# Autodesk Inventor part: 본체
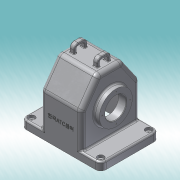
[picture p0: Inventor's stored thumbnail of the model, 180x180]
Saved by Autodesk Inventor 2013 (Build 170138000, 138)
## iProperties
Created: 2016-12
Part Number: 본체
Material: 알루미늄 6061
Document SubType Name: Modeling
Designer: dgall
Density: 2.71 g/cm^3
Mass: 1066.93 g
Surface Area: 1138.58 cm^2
Volume: 393.702 cm^3
Author: dgall
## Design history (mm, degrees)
sketch "스케치1"
  geometry: L1 (-75, 55)-(75, 55); L2 (75, 55)-(75, -55); L3 (75, -55)-(-75, -55); L4 (-75, -55)-(-75, 55); 3 further points
  constraints: 8 end point, 2 midpoint, 2 parallel, 1 horizontal, 1 horizontal alignment, 1 perpendicular, 1 vertical alignment
  dimensions: "d0" = 150 distance of L1.start L1.end; "d2" = 110 distance of L1.end L2.end
extrude "돌출1" new body sketch "스케치1" distance "d3" = 15; taper "d4" = 0 deg
sketch "스케치2"
  geometry: L1 (55, 15)-(-55, 15) reference; L2 (-55, 15)-(-55, 80); L3 (-55, 80)-(-23.491, 125); L4 (-23.491, 125)-(23.491, 125); L5 (23.491, 125)-(55, 80); L6 (55, 80)-(55, 15); L7 (-55, 0)-(55, 0) reference; 3 further points
  constraints: 10 end point, 2 midpoint, 2 perpendicular, 1 horizontal alignment, 1 parallel, 1 vertical alignment
  dimensions: "d5" = 35 deg angle of L2 L3; "d6" = 80 distance from line of L2.end L7; "d7" = 125 distance between parallel lines of L4 L7
extrude "돌출2" join sketch "스케치2" stored distance "d8" = 77; taper "d9" = 0 deg
sketch "스케치3"
  geometry: L1 (-55, 80)-(-23.491, 125) reference; L2 (-23.491, 125)-(23.491, 125) reference; L3 (23.491, 125)-(55, 80) reference; L4 (55, 80)-(55, 15) reference; L5 (-55, 15)-(-55, 80) reference; L6 (-55, 0)-(-55, 15) reference; L7 (55, 0)-(55, 15) reference; L8 (-55, 0)-(55, 0) reference; L9 (20.888, 120)-(-20.888, 120); L10 (-20.888, 120)-(-50, 78.424); L11 (50, 78.424)-(20.888, 120); L12 (-50, 78.424)-(-50, 0); L13 (50, 78.424)-(50, 0); 1 further point
  constraints: 10 end point, 2 perpendicular, 2 point on line, 1 other
  dimensions: "d10" = 5 distance between parallel lines of L3 L11; "d11" = 5 distance between parallel lines of L1 L10; "d12" = 5 distance between parallel lines of L5 L12; "d13" = 5 distance between parallel lines of L4 L13
extrude "돌출3" cut sketch "스케치3" stored distance "d14" = 67; taper "d15" = 0 deg
sketch "스케치4"
  geometry: L1 (-38.5, 80)-(-38.5, 15) reference; L2 (-38.5, 125)-(-38.5, 80) reference; L3 (-43.5, 65)-(-19.5, 65); L4 (-43.5, 65)-(-43.5, 102.5); L5 (-43.5, 102.5)-(-38.5, 102.5); L6 (33.5, 78.424)-(-33.5, 78.424) reference; L7 (33.5, 78.424)-(33.5, 120) reference; L8 (33.5, 120)-(-33.5, 120) reference; L9 (-33.5, 120)-(-33.5, 78.424) reference; L10 (-33.5, 78.424)-(-33.5, 0) reference; L11 (-33.5, 106)-(-19.5, 92); L12 (-19.5, 92)-(-19.5, 65); L13 (-38.5, 102.5)-(-38.5, 106); L14 (-33.5, 106)-(-38.5, 106); 1 further point
  constraints: 14 end point, 4 perpendicular, 2 point on line, 1 midpoint, 1 parallel
  dimensions: "d17" = 65 distance from line of point (0, 0) L3; "d18" = 75 diameter of L5 L3; "d19" = 5 distance of L4.end L5.end; "d20" = 54 diameter of L11.end L3; "d21" = 24 distance of L3.start L3.end; "d22" = 45 deg angle of L12 L11
revolve "회전1" sketch "스케치4" stored, may be unused: angle "d23" = 90 deg
sketch "스케치5"
  geometry: L1 (-43.5, 27.5)-(-43.5, 102.5) reference; L2 (-19.5, 38)-(-19.5, 92) reference; L3 (-19.5, 65)-(-43.5, 65); L4 (-43.5, 85)-(-19.5, 85); L5 (-19.5, 65)-(-19.5, 85); L6 (-43.5, 65)-(-43.5, 85); 1 further point
  constraints: 8 end point, 2 collinear, 2 midpoint, 2 point on line, 1 perpendicular
  dimensions: "d24" = 40 diameter of L4 L3
revolve "회전2" sketch "스케치5" stored, may be unused: angle "d25" = 90 deg
sketch "스케치7"
  geometry: L1 (0, -55)-(0, 55) reference; C1 r 31 at (65, 0); 2 further points
  constraints: 1 centre point, 1 horizontal alignment, 1 midpoint
  dimensions: "d29" = 62 diameter of C1; "d31" = 65 distance from line of C1.centre L1
extrude "돌출4" join sketch "스케치7" distance "d32" = 10; taper "d33" = 0 deg
sketch "스케치9"
  geometry: C1 r 31 at (0, 0) reference; C2 r 20 at (0, 0); 1 further point
  constraints: 1 centre point, 1 coincident
  dimensions: "d34" = 40 diameter of C2
extrude "돌출5" cut sketch "스케치9" stored distance "d36" = 10; taper "d37" = 0 deg
sketch "스케치10"
  geometry: C1 r 20 at (0, 0) reference; 2 further points
  constraints: 1 horizontal alignment
  dimensions: "d38" = 29 distance of C1.centre point (-29, 0)
hole "구멍1" sketch "스케치10" at (-29, 0) diameter "d39" = 2.621; stored, may be unused: countersink angle "d43" = 90 deg, drill point angle "d45" = 118 deg; dims "d40" = 6, "d41" = 4, "d42" = 2, "d44" = 8
sketch "스케치11"
  geometry: C1 r 20 at (0, 0) reference; 2 further points
  constraints: 1 vertical alignment
  dimensions: "d49" = 26 distance of C1.centre point (0, 26)
hole "구멍2" sketch "스케치11" at (0, 26) diameter "d50" = 2.621; stored, may be unused: countersink angle "d54" = 90 deg, drill point angle "d56" = 118 deg; dims "d51" = 6, "d52" = 4, "d53" = 2, "d55" = 8
node "작업 평면2"
  node "작업 평면1"
sketch "스케치12"
  geometry: L1 (125, 23.491)-(125, -23.491) reference; L2 (125, 12.5)-(140, 12.5); L3 (140, 12.5)-(140, -12.5); L4 (140, -12.5)-(125, -12.5); L5 (125, 7.5)-(135, 7.5); L6 (135, 7.5)-(135, -7.5); L7 (135, -7.5)-(125, -7.5); L8 (0, -50)-(0, 50) reference; 3 further points
  constraints: 12 end point, 5 perpendicular, 4 point on line, 2 horizontal alignment, 2 midpoint, 1 parallel
  dimensions: "d61" = 25 distance of L2.end L3.end; "d63" = 15 distance of L5.end L6.end; "d64" = 140 distance between parallel lines of L3 L8; "d65" = 5 distance between parallel lines of L6 L3
extrude "돌출6" join sketch "스케치12" distance "d66" = 8; taper "d67" = 0 deg
fillet "모깎기1" dims "d68" = 10
sketch "스케치14"
  geometry: L1 (75, -45)-(75, 45) reference; L2 (65, 55)-(38.5, 55) reference; L3 (38.5, 55)-(38.5, -55) reference; L4 (38.5, -55)-(65, -55) reference; A1 r 10 centre (-65, -45) between (-75, -45) and (-65, -55) reference; A2 r 10 centre (-65, 45) between (-65, 55) and (-75, 45) reference; A3 r 10 centre (65, -45) between (65, -55) and (75, -45) reference; A4 r 10 centre (65, 45) between (75, 45) and (65, 55) reference; 5 further points
  constraints: 4 coincident
hole "구멍3" sketch "스케치14" at (65, -45), (65, 45), (-65, 45), (-65, -45) diameter "d69" = 5; stored, may be unused: countersink angle "d73" = 90 deg, drill point angle "d75" = 118 deg; dims "d70" = 6, "d71" = 12, "d72" = 5, "d74" = 8
fillet "모깎기2" dims "d76" = 8
fillet "모깎기3" dims "d77" = 3
fillet "모깎기4" dims "d78" = 1
fillet "모깎기5" dims "d79" = 1
fillet "모깎기6" dims "d80" = 10
fillet "모깎기7" dims "d81" = 8
fillet "모깎기8" dims "d82" = 3
sketch "스케치15"
  geometry: L1 (0, 0)-(130, 0) reference; L2 (103.5, -76.847)-(103.5, -18) reference; 2 further points
  constraints: 1 other
  dimensions: "d83" = 38.5 distance from line of point (65, -45) L2; "d84" = 45 distance from line of L1 point (65, -45)
feature "엠보싱1" sketch "스케치15" dims "d0" = 150, "d2" = 110, "d85" = 0.5, "d86" = 0
fillet "모깎기9" dims "d87" = 3
fillet "모깎기10" dims "d88" = 3
fillet "모깎기11" dims "d89" = 3
chamfer "모따기1" distance "d90" = 1; stored, may be unused: second distance "d91" = 2, angle "d92" = 45 deg
node "솔리드1"
pattern_circular "원형 패턴1" dims angle "d47" = 360 deg
pattern_circular "원형 패턴2" dims angle "d58" = 360 deg
mirror "대칭1"
node "투영된 루프1"
node "투영된 루프2"
other parameters: "d60" = 18
